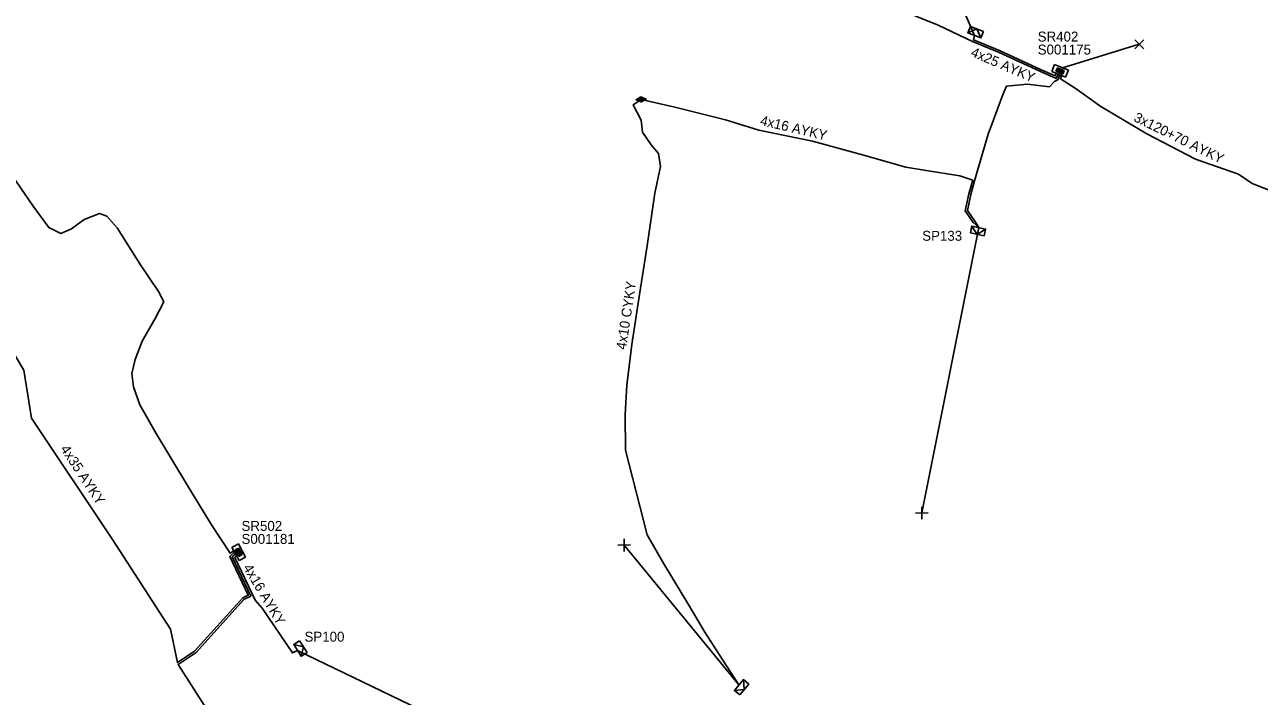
# Model space of a CAD drawing. Extents: x -762504 to -761250, y -1152974 to -1152253.
# Drawn here: x -761655.3 to -761531.9, y -1152391 to -1152323.8 of the extents above; entities that cross this region are included whole.
import ezdxf

# ---------------------------------------------------------------- set-up
doc = ezdxf.new("R2010")
doc.units = 0
for name, color, linetype in [('Vrstva 19', 7, 'Continuous'), ('Vrstva 28', 7, 'Continuous'), ('Vrstva 29', 7, 'Continuous'), ('Vrstva 30', 7, 'Continuous'), ('Vrstva 31', 7, 'Continuous'), ('Vrstva 33', 7, 'Continuous'), ('Vrstva 34', 7, 'Continuous'), ('Vrstva 5', 7, 'Continuous'), ('Vrstva 59', 7, 'Continuous'), ('Vrstva 6', 7, 'Continuous')]:
    doc.layers.add(name, color=color, linetype=linetype)

msp = doc.modelspace()

# ---------------------------------------------------------------- linework, layer by layer
at = {"layer": 'Vrstva 19'}
for points in [[(-761593.724, -1152331.009), (-761594.21, -1152331.287), (-761593.697, -1152331.509), (-761593.211, -1152331.235), (-761593.724, -1152331.009)], [(-761594.08, -1152331.277), (-761593.701, -1152331.446), (-761593.349, -1152331.242), (-761593.72, -1152331.072), (-761594.08, -1152331.277)], [(-761593.954, -1152331.27), (-761593.704, -1152331.383), (-761593.459, -1152331.244), (-761593.717, -1152331.135), (-761593.954, -1152331.27)], [(-761593.832, -1152331.264), (-761593.707, -1152331.32), (-761593.581, -1152331.25), (-761593.714, -1152331.198), (-761593.832, -1152331.264)]]:
    msp.add_lwpolyline(points, dxfattribs=at)
at = {"layer": 'Vrstva 28'}
for points in [[(-761552.358, -1152327.776), (-761552.639, -1152328.472)], [(-761552.639, -1152328.472), (-761551.248, -1152329.034)], [(-761550.967, -1152328.338), (-761552.358, -1152327.776)], [(-761552.073, -1152328.095), (-761552.214, -1152328.446)], [(-761552.214, -1152328.446), (-761551.524, -1152328.725)], [(-761552.047, -1152328.157), (-761552.153, -1152328.42)], [(-761552.153, -1152328.42), (-761551.551, -1152328.663)], [(-761552.021, -1152328.218), (-761552.091, -1152328.394)], [(-761552.091, -1152328.394), (-761551.577, -1152328.602)], [(-761551.383, -1152328.374), (-761552.073, -1152328.095)], [(-761551.444, -1152328.4), (-761552.047, -1152328.157)], [(-761551.995, -1152328.28), (-761552.03, -1152328.367)], [(-761552.03, -1152328.367), (-761551.603, -1152328.54)], [(-761551.506, -1152328.426), (-761552.021, -1152328.218)], [(-761551.567, -1152328.452), (-761551.995, -1152328.28)], [(-761551.623, -1152328.481), (-761551.974, -1152328.339)], [(-761551.603, -1152328.54), (-761551.567, -1152328.452)], [(-761551.577, -1152328.602), (-761551.506, -1152328.426)], [(-761551.551, -1152328.663), (-761551.444, -1152328.4)], [(-761551.524, -1152328.725), (-761551.383, -1152328.374)], [(-761551.248, -1152329.034), (-761550.967, -1152328.338)], [(-761633.972, -1152375.72), (-761634.628, -1152376.084)], [(-761634.628, -1152376.084), (-761633.9, -1152377.396)], [(-761633.951, -1152376.148), (-761634.281, -1152376.331)], [(-761634.281, -1152376.331), (-761633.921, -1152376.982)], [(-761633.969, -1152376.212), (-761634.217, -1152376.349)], [(-761634.217, -1152376.349), (-761633.902, -1152376.917)], [(-761633.988, -1152376.276), (-761634.153, -1152376.368)], [(-761634.153, -1152376.368), (-761633.884, -1152376.853)], [(-761634.006, -1152376.34), (-761634.089, -1152376.386)], [(-761634.089, -1152376.386), (-761633.865, -1152376.789)], [(-761633.844, -1152376.73), (-761634.027, -1152376.399)], [(-761633.783, -1152376.743), (-761634.006, -1152376.34)], [(-761633.719, -1152376.762), (-761633.988, -1152376.276)], [(-761633.245, -1152377.032), (-761633.972, -1152375.72)], [(-761633.654, -1152376.78), (-761633.969, -1152376.212)], [(-761633.59, -1152376.798), (-761633.951, -1152376.148)], [(-761633.921, -1152376.982), (-761633.59, -1152376.798)], [(-761633.902, -1152376.917), (-761633.654, -1152376.78)], [(-761633.9, -1152377.396), (-761633.245, -1152377.032)], [(-761633.884, -1152376.853), (-761633.719, -1152376.762)], [(-761633.865, -1152376.789), (-761633.783, -1152376.743)]]:
    msp.add_lwpolyline(points, dxfattribs=at)
at = {"layer": 'Vrstva 31'}
for points in [[(-761559.463, -1152324.458), (-761559.714, -1152325.112), (-761561.021, -1152324.61), (-761560.77, -1152323.956)], [(-761560.116, -1152324.207), (-761561.021, -1152324.61)], [(-761559.463, -1152324.458), (-761560.77, -1152323.956)], [(-761560.116, -1152324.207), (-761559.714, -1152325.112)], [(-761560.773, -1152344.619), (-761560.628, -1152343.934), (-761559.258, -1152344.225), (-761559.404, -1152344.91)], [(-761560.088, -1152344.764), (-761560.628, -1152343.934)], [(-761560.088, -1152344.764), (-761559.258, -1152344.225)], [(-761560.773, -1152344.619), (-761559.404, -1152344.91)], [(-761627.104, -1152386.595), (-761627.697, -1152386.966), (-761628.439, -1152385.779), (-761627.845, -1152385.408)], [(-761627.475, -1152386.001), (-761628.439, -1152385.779)], [(-761627.104, -1152386.595), (-761627.845, -1152385.408)], [(-761627.475, -1152386.001), (-761627.697, -1152386.966)], [(-761583.835, -1152390.819), (-761584.372, -1152390.369), (-761583.472, -1152389.296), (-761582.935, -1152389.746)], [(-761583.835, -1152390.819), (-761582.935, -1152389.746)], [(-761583.385, -1152390.282), (-761583.472, -1152389.296)], [(-761583.385, -1152390.282), (-761584.372, -1152390.369)]]:
    msp.add_lwpolyline(points, dxfattribs=at)
at = {"layer": 'Vrstva 34'}
for points in [[(-761544.322, -1152325.308), (-761543.438, -1152326.192)], [(-761544.322, -1152326.192), (-761543.438, -1152325.308)], [(-761566.255, -1152372.641), (-761565.005, -1152372.619)], [(-761565.619, -1152373.255), (-761565.641, -1152372.005)], [(-761595.379, -1152376.465), (-761595.401, -1152375.215)], [(-761596.015, -1152375.851), (-761594.765, -1152375.829)]]:
    msp.add_lwpolyline(points, dxfattribs=at)
at = {"layer": 'Vrstva 5'}
for points in [[(-761568.45, -1152322.04), (-761563.99, -1152323.83), (-761560.55, -1152325.48), (-761557.89, -1152326.58), (-761553.84, -1152328.44), (-761552.2, -1152329.18), (-761552.01, -1152328.72)], [(-761552.2, -1152328.65), (-761552.3, -1152328.91), (-761553.76, -1152328.26), (-761557.81, -1152326.4), (-761560.47, -1152325.29), (-761560.37, -1152324.86)], [(-761551.83, -1152328.8), (-761552.01, -1152329.26), (-761552.37, -1152329.47), (-761552.86, -1152330), (-761555.06, -1152329.73), (-761557.16, -1152329.93), (-761557.5, -1152330.71), (-761559.01, -1152334.74), (-761560.35, -1152339.41), (-761560.74, -1152340.76), (-761561.06, -1152342.37), (-761560.32, -1152343.44), (-761559.94, -1152344.08), (-761560.48, -1152343.56), (-761561.28, -1152342.41), (-761560.94, -1152340.72), (-761560.54, -1152339.35), (-761561.83, -1152338.89), (-761565.2, -1152338.36), (-761567.24, -1152338.04), (-761571.57, -1152336.8), (-761576.57, -1152335.43), (-761581.93, -1152334.35), (-761585.27, -1152333.29), (-761590.33, -1152332.03), (-761593.71, -1152331.26)], [(-761551.64, -1152328.87), (-761551.77, -1152329.2), (-761550.31, -1152330.15), (-761547.72, -1152331.96), (-761543.14, -1152334.7), (-761538.27, -1152337.24), (-761533.97, -1152338.75), (-761532.59, -1152339.66), (-761529.29, -1152340.97), (-761525.62, -1152341.97), (-761521, -1152342.51), (-761519.85, -1152342.17), (-761519.4, -1152342.07), (-761519.32, -1152342.41), (-761518.44, -1152342.5), (-761517.37, -1152342.76), (-761517.11, -1152342.14)], [(-761583.92, -1152389.83), (-761585.52, -1152387.35), (-761587.34, -1152384.56), (-761588.94, -1152381.84), (-761591.43, -1152377.73), (-761593.1, -1152374.83), (-761595.25, -1152366.34), (-761595.29, -1152362.79), (-761595.13, -1152359.86), (-761594.62, -1152355.79), (-761593.86, -1152350.77), (-761593.11, -1152345.89), (-761592.32, -1152340.65), (-761591.77, -1152337.96), (-761591.97, -1152336.68), (-761592.68, -1152335.8), (-761593.55, -1152334.52), (-761593.69, -1152333.35), (-761594.49, -1152331.79), (-761593.71, -1152331.26)], [(-761634.35, -1152376.55), (-761634.84, -1152376.97), (-761632.99, -1152380.85), (-761633.54, -1152381.11), (-761638.35, -1152386.44), (-761640.07, -1152387.6), (-761640.77, -1152384.25), (-761646.56, -1152375.28), (-761654.67, -1152363.13), (-761655.44, -1152358.33), (-761660.7, -1152349.53), (-761666.67, -1152339.99), (-761669.92, -1152334.61), (-761672.1, -1152336.22)], [(-761634.44, -1152376.4), (-761634.8, -1152376.64), (-761636.65, -1152373.8), (-761639.05, -1152369.88), (-761642.18, -1152364.69), (-761643.83, -1152361.82), (-761644.45, -1152360.02), (-761644.62, -1152358.68), (-761644.3, -1152357.26), (-761643.61, -1152355.44), (-761642.31, -1152353.16), (-761641.44, -1152351.52), (-761641.95, -1152350.47), (-761643.77, -1152347.82), (-761646.1, -1152344.1), (-761647.12, -1152342.94), (-761647.86, -1152342.68), (-761649.38, -1152343.28), (-761650.67, -1152344.21), (-761651.72, -1152344.67), (-761652.94, -1152344.08), (-761654.51, -1152341.94), (-761656.95, -1152338.33)], [(-761636.56, -1152393.15), (-761640, -1152387.78), (-761638.21, -1152386.6), (-761633.42, -1152381.27), (-761632.73, -1152380.94), (-761634.59, -1152377.02), (-761634.26, -1152376.74)], [(-761634.13, -1152376.89), (-761634.34, -1152377.07), (-761632.31, -1152381.35), (-761631.58, -1152382.14), (-761628.57, -1152386.63), (-761628.07, -1152386.37)]]:
    msp.add_lwpolyline(points, dxfattribs=at)
at = {"layer": 'Vrstva 59'}
for points in [[(-761560.37, -1152324.86), (-761564.88, -1152314.38)], [(-761551.66, -1152328.14), (-761543.88, -1152325.75)], [(-761559.94, -1152344.08), (-761565.63, -1152372.63)], [(-761583.92, -1152389.83), (-761595.39, -1152375.84)], [(-761628.07, -1152386.37), (-761606.56, -1152396.75)]]:
    msp.add_lwpolyline(points, dxfattribs=at)

# ---------------------------------------------------------------- texts
at = {"layer": 'Vrstva 29'}
for s, p in [('S001175', (-761554.04, -1152326.77)), ('S001181', (-761633.66, -1152375.72))]:
    msp.add_text(s, height=0.9943, dxfattribs=at).set_placement(p)
at = {"layer": 'Vrstva 30'}
for s, p in [('SR402', (-761554.04, -1152325.47)), ('SR502', (-761633.66, -1152374.42))]:
    msp.add_text(s, height=0.9943, dxfattribs=at).set_placement(p)
at = {"layer": 'Vrstva 33'}
for s, p in [('SP133', (-761565.59, -1152345.4)), ('SP100', (-761627.36, -1152385.5))]:
    msp.add_text(s, height=0.9943, dxfattribs=at).set_placement(p)
at = {"layer": 'Vrstva 6'}
for s, height, rotation, p in [('4x25 AYKY', 0.9943, 336.84491, (-761560.82, -1152326.9)), ('4x16 AYKY', 0.9943, 346.81424, (-761581.86, -1152333.81)), ('3x120+70 AYKY', 0.99429, 333.80902, (-761544.52, -1152333.39)), ('4x10 CYKY', 0.9943, 81.40409, (-761595.22, -1152356.34)), ('4x35 AYKY', 0.9943, 303.48984, (-761651.82, -1152366.23)), ('4x16 AYKY', 0.9943, 300.73544, (-761633.54, -1152378.09))]:
    msp.add_text(s, height=height, rotation=rotation, dxfattribs=at).set_placement(p)

doc.saveas('drawing.dxf')
